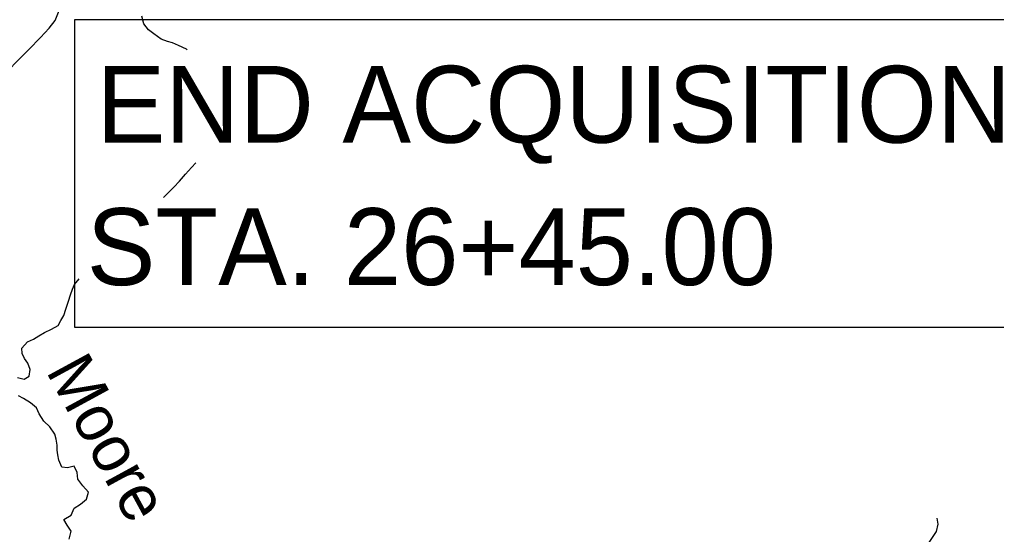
# Model space of a CAD drawing. Extents: x 5.6 to 39.6, y 0.7 to 22.7.
# Drawn here: x 9.058 to 11.039, y 16.946 to 17.991 of the extents above; entities that cross this region are included whole.
import ezdxf

# ---------------------------------------------------------------- set-up
doc = ezdxf.new("R2010")
doc.units = 0
doc.layers.add('Default', color=7, linetype='Continuous')
doc.layers.add('SH_Data', color=7, linetype='Continuous')

msp = doc.modelspace()

# ---------------------------------------------------------------- linework, layer by layer
at = {"layer": 'Default'}
for points in [[(8.2918, 17.3553), (8.33, 17.3641), (8.3628, 17.3766), (8.3836, 17.3856), (8.4076, 17.3992), (8.4372, 17.4203), (8.5113, 17.4753), (8.5493, 17.5092), (8.5961, 17.5466), (8.6467, 17.5861), (8.6721, 17.608), (8.6896, 17.6201), (8.7071, 17.6295), (8.7348, 17.6418), (8.7655, 17.6599), (8.7971, 17.6825), (8.8834, 17.753), (9.0116, 17.8654), (9.0767, 17.9304), (9.1006, 17.9549), (9.1182, 17.9742), (9.13, 17.9897), (9.138, 18.0094)], [(9.3981, 17.9301), (9.3965, 17.931), (9.3806, 17.9388), (9.3678, 17.9439), (9.358, 17.947), (9.3448, 17.9518), (9.3301, 17.9622), (9.3196, 17.9703), (9.3103, 17.9829), (9.3056, 17.9981)], [(9.3502, 17.63), (9.3593, 17.6396), (9.3705, 17.6512), (9.382, 17.6636), (9.3946, 17.6775), (9.4069, 17.691), (9.4151, 17.7006)], [(9.0537, 17.2651), (9.067, 17.2611), (9.0776, 17.2678), (9.0797, 17.2811), (9.0745, 17.2937), (9.0682, 17.3032), (9.063, 17.3135), (9.0628, 17.3242), (9.0743, 17.3369), (9.0861, 17.3429), (9.0972, 17.3492), (9.1086, 17.3563), (9.1227, 17.3626), (9.1361, 17.3704), (9.1415, 17.3806), (9.1477, 17.3907), (9.152, 17.4036), (9.1571, 17.4198), (9.1614, 17.4323), (9.1653, 17.444), (9.1696, 17.4539), (9.1786, 17.4649)], [(9.1587, 16.9367), (9.1623, 16.9526), (9.1545, 16.9648), (9.1478, 16.9767), (9.1623, 16.9856), (9.1689, 16.9999), (9.1815, 17.0078), (9.1938, 17.0179), (9.1977, 17.0322), (9.1865, 17.0449), (9.176, 17.0583), (9.1751, 17.072), (9.1684, 17.085), (9.1555, 17.0813), (9.1434, 17.083), (9.1375, 17.0971), (9.1353, 17.1081), (9.1343, 17.1176), (9.134, 17.1275), (9.1319, 17.1397), (9.1293, 17.1499), (9.1197, 17.1648), (9.1073, 17.176), (9.098, 17.1913), (9.0921, 17.2035), (9.0804, 17.2131), (9.0661, 17.2224), (9.0556, 17.2275)], [(9.1605, 16.3581), (9.1651, 16.3637), (9.1749, 16.3682), (9.1874, 16.3659), (9.2074, 16.3517), (9.2618, 16.3336), (9.4481, 16.3211), (9.6428, 16.3196), (9.956, 16.3235), (9.9746, 16.3245), (10.0103, 16.3372), (10.475, 16.6545), (10.5609, 16.706), (10.6587, 16.7813), (10.7891, 16.8599), (10.8343, 16.8896), (10.8575, 16.9024), (10.8806, 16.9114), (10.9027, 16.9302), (10.9176, 16.9521), (10.9207, 16.9673), (10.9185, 16.9795)]]:
    msp.add_lwpolyline(points, dxfattribs=at)
at = {"layer": 'SH_Data'}
msp.add_lwpolyline([(9.1704, 17.9914), (11.2799, 17.9914), (11.2799, 17.3664), (9.1704, 17.3664)], close=True, dxfattribs=at)

# ---------------------------------------------------------------- texts
at = {"layer": 'Default'}
msp.add_text('Moore', height=0.09472, rotation=298.5594, dxfattribs=at).set_placement((9.1104, 17.278))
at = {"layer": 'SH_Data'}
msp.add_text('END ACQUISITION', height=0.156, rotation=360, dxfattribs=at).set_placement((9.2143, 17.7414))
msp.add_text('STA. 26+45.00', height=0.156, dxfattribs=at).set_placement((9.1942, 17.4524))

doc.saveas('drawing.dxf')
